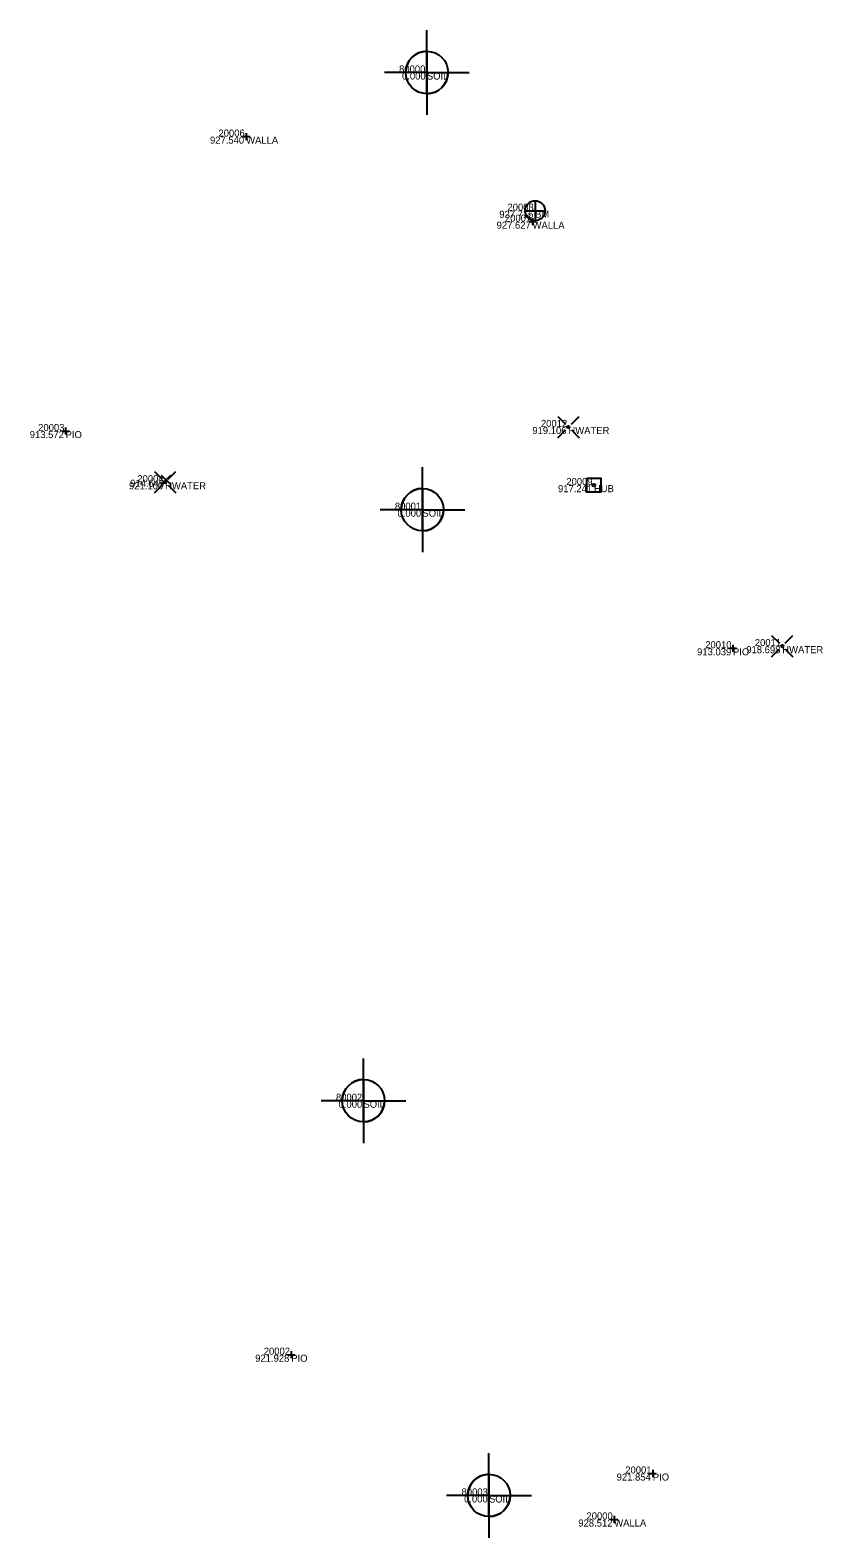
# Model space of a CAD drawing. Extents: x 1722873 to 1722986, y 330931 to 331145.
import ezdxf

# ---------------------------------------------------------------- set-up
doc = ezdxf.new("R2010")
doc.units = 0
for name, color, linetype in [('DR_X_Cells', 7, 'Continuous'), ('GE_X_Cells', 7, 'Continuous'), ('GK_Drainage_Nodes', 7, 'Continuous'), ('SV_X_Control_Cells_Found', 7, 'Continuous'), ('SV_X_Shot_Marker', 7, 'Continuous'), ('SV_X_Text_Comment', 7, 'Continuous'), ('SV_X_Text_Elevation', 7, 'Continuous'), ('SV_X_Text_Name', 7, 'Continuous'), ('UT_X_Telecom_Cells', 7, 'Continuous')]:
    doc.layers.add(name, color=color, linetype=linetype)

msp = doc.modelspace()

# ---------------------------------------------------------------- linework, layer by layer
at = {"layer": 'DR_X_Cells'}
for p, q in [((1722943.56, 331119.12), (1722946.39, 331119.12)), ((1722944.97, 331120.53), (1722944.97, 331117.71)), ((1722948.18, 331089.99), (1722949.27, 331088.9)), ((1722950.1, 331088.9), (1722951.19, 331089.99)), ((1722948.18, 331086.97), (1722949.27, 331088.06)), ((1722950.1, 331088.06), (1722951.19, 331086.97)), ((1722891.09, 331082.16), (1722892.19, 331081.07)), ((1722893.02, 331081.07), (1722894.11, 331082.16)), ((1722891.09, 331079.14), (1722892.19, 331080.24)), ((1722893.02, 331080.24), (1722894.11, 331079.14)), ((1722978.45, 331058.95), (1722979.55, 331057.85)), ((1722978.45, 331055.93), (1722979.55, 331057.02)), ((1722980.38, 331057.85), (1722981.47, 331058.95)), ((1722980.38, 331057.02), (1722981.47, 331055.93))]:
    msp.add_line(p, q, dxfattribs=at)
msp.add_lwpolyline([(1722952.3, 331081.24), (1722954.28, 331081.24), (1722954.28, 331079.26), (1722952.3, 331079.26), (1722952.3, 331081.24)], dxfattribs=at)
for centre, radius in [((1722944.97, 331119.12), 1.41), ((1722949.69, 331088.49), 0.17), ((1722892.6, 331080.66), 0.17), ((1722953.29, 331080.25), 0.2), ((1722979.96, 331057.44), 0.17)]:
    msp.add_circle(centre, radius, dxfattribs=at)
at = {"layer": 'GE_X_Cells'}
for p, q in [((1722904.07, 331130.12), (1722904.07, 331129.12)), ((1722903.57, 331129.62), (1722904.57, 331129.62)), ((1722904.07, 331129.62), (1722904.07, 331129.62)), ((1722944.11, 331117.57), (1722945.11, 331117.57)), ((1722944.61, 331118.07), (1722944.61, 331117.07)), ((1722944.61, 331117.57), (1722944.61, 331117.57)), ((1722955.67, 330933.73), (1722956.67, 330933.73)), ((1722956.17, 330934.23), (1722956.17, 330933.23)), ((1722956.17, 330933.73), (1722956.17, 330933.73))]:
    msp.add_line(p, q, dxfattribs=at)
at = {"layer": 'GK_Drainage_Nodes'}
for p, q in [((1722892.06, 331080.34), (1722893.39, 331081.68)), ((1722892.06, 331081.68), (1722893.39, 331080.34))]:
    msp.add_line(p, q, dxfattribs=at)
at = {"layer": 'SV_X_Shot_Marker'}
for p, q in [((1722929.65, 331138.7), (1722929.65, 331144.7)), ((1722929.65, 331141.7), (1722929.65, 331138.7)), ((1722929.65, 331138.7), (1722923.65, 331138.7)), ((1722929.65, 331138.7), (1722926.65, 331138.7)), ((1722929.65, 331138.7), (1722929.65, 331132.7)), ((1722929.65, 331138.7), (1722935.65, 331138.7)), ((1722929.65, 331135.7), (1722929.65, 331138.7)), ((1722929.65, 331138.7), (1722932.65, 331138.7)), ((1722929.02, 331076.77), (1722929.02, 331082.77)), ((1722929.02, 331079.77), (1722929.02, 331076.77)), ((1722929.02, 331076.77), (1722923.02, 331076.77)), ((1722929.02, 331076.77), (1722926.02, 331076.77)), ((1722929.02, 331076.77), (1722929.02, 331070.77)), ((1722929.02, 331076.77), (1722935.02, 331076.77)), ((1722929.02, 331073.77), (1722929.02, 331076.77)), ((1722929.02, 331076.77), (1722932.02, 331076.77)), ((1722920.67, 330993.05), (1722920.67, 330999.05)), ((1722920.67, 330996.05), (1722920.67, 330993.05)), ((1722920.67, 330993.05), (1722914.67, 330993.05)), ((1722920.67, 330993.05), (1722917.67, 330993.05)), ((1722920.67, 330993.05), (1722920.67, 330987.05)), ((1722920.67, 330993.05), (1722926.67, 330993.05)), ((1722920.67, 330990.05), (1722920.67, 330993.05)), ((1722920.67, 330993.05), (1722923.67, 330993.05)), ((1722938.44, 330937.13), (1722938.44, 330943.13)), ((1722938.44, 330940.13), (1722938.44, 330937.13)), ((1722938.44, 330937.13), (1722932.44, 330937.13)), ((1722938.44, 330937.13), (1722935.44, 330937.13)), ((1722938.44, 330937.13), (1722938.44, 330931.13)), ((1722938.44, 330937.13), (1722944.44, 330937.13)), ((1722938.44, 330934.13), (1722938.44, 330937.13)), ((1722938.44, 330937.13), (1722941.44, 330937.13))]:
    msp.add_line(p, q, dxfattribs=at)
for centre in [(1722929.65, 331138.7), (1722929.02, 331076.77), (1722920.67, 330993.05), (1722938.44, 330937.13)]:
    msp.add_circle(centre, 3, dxfattribs=at)
for centre, start, end in [((1722929.65, 331138.7), 90, 180), ((1722929.65, 331138.7), 270, 360), ((1722929.02, 331076.77), 90, 180), ((1722929.02, 331076.77), 270, 360), ((1722920.67, 330993.05), 90, 180), ((1722920.67, 330993.05), 270, 360), ((1722938.44, 330937.13), 90, 180), ((1722938.44, 330937.13), 270, 360)]:
    msp.add_arc(centre, 3, start, end, dxfattribs=at)
at = {"layer": 'SV_X_Text_Elevation'}
for p, q in [((1722878.01, 331087.91), (1722879.01, 331087.91)), ((1722878.51, 331088.41), (1722878.51, 331087.41)), ((1722878.51, 331087.91), (1722878.51, 331087.91)), ((1722972.48, 331057.14), (1722973.48, 331057.14)), ((1722972.98, 331057.64), (1722972.98, 331056.64)), ((1722972.98, 331057.14), (1722972.98, 331057.14)), ((1722909.95, 330957.07), (1722910.95, 330957.07)), ((1722910.45, 330957.57), (1722910.45, 330956.57)), ((1722910.45, 330957.07), (1722910.45, 330957.07)), ((1722961.13, 330940.24), (1722962.13, 330940.24)), ((1722961.63, 330940.74), (1722961.63, 330939.74)), ((1722961.63, 330940.24), (1722961.63, 330940.24))]:
    msp.add_line(p, q, dxfattribs=at)

# ---------------------------------------------------------------- texts
at = {"layer": 'SV_X_Control_Cells_Found'}
for s, p in [('0.000', (1722926.13, 331137.7)), ('927.715', (1722939.9, 331118.12)), ('913.572', (1722873.44, 331086.91)), ('919.106', (1722944.58, 331087.49)), ('921.100', (1722887.49, 331079.66)), ('914.649', (1722887.64, 331080.01)), ('917.241', (1722948.21, 331079.25)), ('0.000', (1722925.5, 331075.77)), ('913.039', (1722967.9, 331056.14)), ('918.698', (1722974.86, 331056.44)), ('0.000', (1722917.15, 330992.05)), ('921.928', (1722905.35, 330956.07)), ('921.854', (1722956.51, 330939.24)), ('0.000', (1722934.92, 330936.13))]:
    msp.add_text(s, height=1, dxfattribs=at).set_placement(p)
at = {"layer": 'SV_X_Text_Comment'}
for s, p in [('80000', (1722925.72, 331138.7)), ('20008', (1722941.06, 331119.12)), ('20012', (1722945.8, 331088.49)), ('20003', (1722874.63, 331087.91)), ('20004', (1722888.66, 331080.66)), ('20009', (1722949.39, 331080.25)), ('80001', (1722925.12, 331076.77)), ('20010', (1722969.05, 331057.14)), ('20011', (1722976.07, 331057.44)), ('80002', (1722916.78, 330993.05)), ('20002', (1722906.56, 330957.07)), ('20001', (1722957.73, 330940.24)), ('80003', (1722934.56, 330937.13))]:
    msp.add_text(s, height=1, dxfattribs=at).set_placement(p)
at = {"layer": 'SV_X_Text_Name'}
for s, p in [('927.540', (1722898.95, 331128.62)), ('20006', (1722900.15, 331129.62)), ('WALLA', (1722904.07, 331128.62)), ('927.627', (1722939.52, 331116.57)), ('20007', (1722940.7, 331117.57)), ('WALLA', (1722944.61, 331116.57)), ('928.512', (1722951.09, 330932.73)), ('20000', (1722952.24, 330933.73)), ('WALLA', (1722956.17, 330932.73))]:
    msp.add_text(s, height=1, dxfattribs=at).set_placement(p)
at = {"layer": 'UT_X_Telecom_Cells'}
for s, p in [('SOIL', (1722929.65, 331137.7)), ('BM', (1722944.97, 331118.12)), ('PIO', (1722878.51, 331086.91)), ('HWATER', (1722949.69, 331087.49)), ('HWATER', (1722892.6, 331079.66)), ('HUB', (1722953.29, 331079.25)), ('SOIL', (1722929.02, 331075.77)), ('PIO', (1722972.98, 331056.14)), ('HWATER', (1722979.96, 331056.44)), ('SOIL', (1722920.67, 330992.05)), ('PIO', (1722910.45, 330956.07)), ('PIO', (1722961.63, 330939.24)), ('SOIL', (1722938.44, 330936.13))]:
    msp.add_text(s, height=1, dxfattribs=at).set_placement(p)

doc.saveas('drawing.dxf')
